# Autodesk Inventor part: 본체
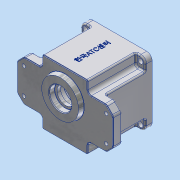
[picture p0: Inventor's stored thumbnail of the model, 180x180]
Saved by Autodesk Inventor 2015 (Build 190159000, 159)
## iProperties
Created: 2016-02
Part Number: 본체
Material: Aluminum 6061
Document SubType Name: Modeling
Designer: Administrator
Density: 2.7 g/cm^3
Appearance: Aluminum - Flat
Mass: 873.756 g
Surface Area: 761.195 cm^2
Volume: 323.613 cm^3
Author: Administrator
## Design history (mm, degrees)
sketch "Sketch1"
  geometry: L1 (70, -30)-(-70, -30); L2 (-70, -30)-(-70, 30); L3 (-70, 30)-(70, 30); L4 (70, 30)-(70, -30); L5 (70, -30)-(-70, 30); L6 (-70, -30)-(70, 30); 1 further point
  constraints: 12 end point, 2 midpoint, 2 parallel, 1 horizontal, 1 perpendicular
  dimensions: "d0" = 140 distance of L2.end L3.end; "d1" = 60 distance of L1.end L2.end
extrude "Extrusion1" new body sketch "Sketch1" distance "d2" = 13; taper "d3" = 0 deg
chamfer "Chamfer1" distance "d4" = 10; stored, may be unused: second distance "d5" = 2, angle "d6" = 45 deg
sketch "Sketch2"
  geometry: L1 (47, -47)-(-47, -47); L2 (-47, -47)-(-47, 47); L3 (-47, 47)-(47, 47); L4 (47, 47)-(47, -47); L5 (47, -47)-(-47, 47); L6 (-47, -47)-(47, 47); 1 further point
  constraints: 12 end point, 2 midpoint, 2 parallel, 1 horizontal, 1 perpendicular
  dimensions: "d7" = 94 distance of L2.end L3.end; "d8" = 94 distance of L1.end L2.end
extrude "Extrusion2" join sketch "Sketch2" distance "d9" = 80; taper "d10" = 0 deg
fillet "Fillet1" dims "d11" = 5
sketch "Sketch3"
  geometry: L1 (-47, 47)-(-47, 30) reference; L2 (-47, 30)-(-57.929, 30) reference; L3 (-57.929, -30)-(-47, -30) reference; L4 (-47, -30)-(-47, -47) reference; L5 (47, -47)-(47, -30) reference; L6 (47, -30)-(57.929, -30) reference; L7 (57.929, 30)-(47, 30) reference; L8 (47, 30)-(47, 47) reference; L9 (47, 30)-(33, 30); L10 (33, 47)-(33, 30); L11 (33, -47)-(33, -30); L12 (47, -30)-(33, -30); L13 (-33, -47)-(-33, -30); L14 (-33, 47)-(-33, 30); L15 (-47, 30)-(-33, 30); L16 (-47, -30)-(-33, -30); L17 (-47, 30)-(-47, 47); L18 (-47, 47)-(-33, 47); L19 (47, 47)-(-47, 47) reference; L20 (33, 47)-(47, 47); L21 (47, 47)-(47, 30); L22 (47, -30)-(47, -47); L23 (47, -47)-(33, -47); L24 (-47, -47)-(47, -47) reference; L25 (-33, -47)-(-47, -47); L26 (-47, -47)-(-47, -30); 1 further point
  constraints: 32 end point, 8 collinear, 4 horizontal
  dimensions: "d12" = 14 distance between parallel lines of L8 L10; "d13" = 14 distance between parallel lines of L5 L11; "d14" = 14 distance between parallel lines of L4 L13; "d15" = 14 distance between parallel lines of L1 L14
extrude "Extrusion3" cut sketch "Sketch3" distance "d16" = 70; taper "d17" = 0 deg
fillet "Fillet2" dims "d18" = 8
sketch "Sketch4"
  geometry: L1 (-60, -19)-(60, -19); L2 (60, -19)-(60, 19); L3 (60, 19)-(-60, 19); L4 (-60, 19)-(-60, -19); L5 (-60, -19)-(60, 19); L6 (60, -19)-(-60, 19); 5 further points
  constraints: 12 end point, 4 coincident, 2 midpoint, 2 parallel, 1 horizontal, 1 perpendicular
  dimensions: "d19" = 120 distance of L3.end L2.end; "d20" = 38 distance of L2.end L1.end
hole "Hole1" sketch "Sketch4" at (-60, 19), (-60, -19), (60, -19), (60, 19) diameter "d21" = 5; stored, may be unused: countersink angle "d25" = 90 deg, drill point angle "d27" = 0 deg; dims "d22" = 6, "d23" = 4, "d24" = 2, "d26" = 9
hole "Hole2" diameter "d30" = 9; stored, may be unused: countersink angle "d34" = 90 deg, drill point angle "d36" = 0 deg; dims "d28" = 10, "d29" = 10, "d31" = 6, "d32" = 4, "d33" = 2, "d35" = 4
hole "Hole3" diameter "d39" = 9; stored, may be unused: countersink angle "d43" = 90 deg, drill point angle "d45" = 0 deg; dims "d37" = 10, "d38" = 10, "d40" = 6, "d41" = 4, "d42" = 2, "d44" = 4
hole "Hole4" diameter "d48" = 9; stored, may be unused: countersink angle "d52" = 90 deg, drill point angle "d54" = 0 deg; dims "d46" = 10, "d47" = 10, "d49" = 6, "d50" = 4, "d51" = 2, "d53" = 4
hole "Hole5" diameter "d57" = 9; stored, may be unused: countersink angle "d61" = 90 deg, drill point angle "d63" = 0 deg; dims "d55" = 10, "d56" = 10, "d58" = 6, "d59" = 4, "d60" = 2, "d62" = 4
sketch "Sketch5"
  geometry: L1 (-40, -40)-(40, -40); L2 (40, -40)-(40, 40); L3 (40, 40)-(-40, 40); L4 (-40, 40)-(-40, -40); L5 (-40, -40)-(40, 40); L6 (40, -40)-(-40, 40); 5 further points
  constraints: 12 end point, 4 coincident, 2 midpoint, 2 parallel, 1 horizontal, 1 perpendicular
  dimensions: "d64" = 80 distance of L3.end L2.end; "d65" = 80 distance of L2.end L1.end
hole "Hole6" sketch "Sketch5" at (-40, 40), (-40, -40), (40, -40), (40, 40) diameter "d66" = 7; stored, may be unused: countersink angle "d70" = 90 deg, drill point angle "d72" = 0 deg; dims "d67" = 6, "d68" = 4, "d69" = 2, "d71" = 4
sketch "Sketch6"
  geometry: 2 further points
  constraints: 1 coincident
hole "Hole7" sketch "Sketch6" at (0, 0) diameter "d73" = 80; stored, may be unused: countersink angle "d77" = 90 deg, drill point angle "d79" = 0 deg; dims "d74" = 6, "d75" = 86, "d76" = 9, "d78" = 71
sketch "Sketch7"
  geometry: C1 r 28 at (0, 11); 1 further point
  constraints: 1 centre point, 1 vertical alignment
  dimensions: "d80" = 56 diameter of C1; "d81" = 11 distance of point (0, 0) C1.centre
extrude "Extrusion4" join sketch "Sketch7" distance "d82" = 7; taper "d83" = -10 deg
sketch "Sketch8"
  geometry: C1 r 21 at (0, -11); C2 r 15 at (0, 20); 1 further point
  constraints: 2 centre point, 2 vertical alignment
  dimensions: "d84" = 21 radius of C1; "d85" = 15 radius of C2; "d86" = 11 distance of point (0, 0) C1.centre; "d87" = 20 distance of C2.centre point (0, 0)
extrude "Extrusion5" join sketch "Sketch8" distance "d88" = 7; taper "d89" = 0 deg
sketch "Sketch9"
  geometry: L1 (36, 0)-(-36, 0); A1 r 36 centre (0, 0) between (-36, 0) and (36, 0); A2 r 4 centre (36, 0) between (35.852, 3.997) and (35.852, -3.997); A3 r 4 centre (-36, 0) between (-35.852, -3.997) and (-35.852, 3.997); A4 r 40 centre (0, 0) between (-39.148, 8.214) and (-39.148, -8.214) reference; A5 r 3.5 centre (-35.722, -7.495) between (-35.778, -3.995) and (-39.148, -8.214); A6 r 3.5 centre (-35.722, 7.495) between (-39.148, 8.214) and (-35.778, 3.995); A7 r 3.5 centre (35.722, -7.495) between (39.148, -8.214) and (35.778, -3.995); A8 r 3.5 centre (35.722, 7.495) between (35.778, 3.995) and (39.148, 8.214); 2 further points
  constraints: 26 point on circle, 8 tangent, 7 centre point, 4 coincident, 2 end point, 1 equal radius, 1 horizontal, 1 midpoint
  dimensions: "d90" = 36 radius of A1; "d91" = 4 radius of A2; "d92" = 4 radius of A3; "d93" = 3.5 radius of A5; "d94" = 3.5 radius of A6; "d95" = 3.5 radius of A7
extrude "Extrusion6" join sketch "Sketch9" stored distance "d96" = 7; taper "d97" = 0 deg
hole "Hole8" diameter "d100" = 25; stored, may be unused: countersink angle "d104" = 90 deg, drill point angle "d106" = 0 deg; dims "d98" = 10, "d99" = 10, "d101" = 6, "d102" = 35, "d103" = 10, "d105" = 15
hole "Hole9" diameter "d109" = 32; stored, may be unused: countersink angle "d113" = 90 deg, drill point angle "d115" = 0 deg; dims "d107" = 10, "d108" = 10, "d110" = 6, "d111" = 35, "d112" = 10, "d114" = 8
fillet "Fillet3" dims "d119" = 0.3
hole "Hole10" diameter "d122" = 19; stored, may be unused: countersink angle "d126" = 90 deg, drill point angle "d128" = 0 deg; dims "d120" = 10, "d121" = 10, "d123" = 6, "d124" = 22, "d125" = 7, "d127" = 8
fillet "Fillet4" dims "d129" = 0.3
fillet "Fillet5" dims "d130" = 2
fillet "Fillet6" dims "d131" = 5
sketch "Sketch11"
  geometry: L1 (36, 0)-(-36, 0); A1 r 36 centre (0, 0) between (36, 0) and (-36, 0); 4 further points
  constraints: 4 coincident, 2 end point, 2 point on circle, 1 centre point, 1 horizontal, 1 midpoint
  dimensions: "d132" = 36 radius of A1
hole "Hole11" sketch "Sketch11" at (36, 0), (-36, 0) diameter "d133" = 3.242; stored, may be unused: countersink angle "d137" = 90 deg, drill point angle "d139" = 118 deg; dims "d134" = 7, "d135" = 22, "d136" = 7, "d138" = 9
fillet "Fillet7" dims "d140" = 3
fillet "Fillet8" dims "d141" = 2
fillet "Fillet9" dims "d142" = 2
sketch "Sketch12"
  geometry: L1 (70, -80)-(8, -80) reference; L2 (0, 0)-(78, 0) reference; 3 further points
  constraints: 1 midpoint, 1 vertical alignment, 1 other
  dimensions: "d143" = 40 distance from line of L2 point (39, -40)
emboss "Emboss1" sketch "Sketch12" dims "d11" = 5, "d144" = 0.5, "d145" = 0
chamfer "Chamfer3" distance "d146" = 1; stored, may be unused: second distance "d147" = 2, angle "d148" = 45 deg
sketch "Sketch14"
  geometry: L1 (31, 47)-(-31, 47) reference; L2 (-33, 45)-(-33, 35) reference; L3 (-38, 30)-(-57.929, 30) reference; L4 (-68.536, 21.464)-(-61.464, 28.536) reference; L5 (-70, 17.929)-(-70, -17.929) reference; L6 (-61.464, -28.536)-(-68.536, -21.464) reference; L7 (-57.929, -30)-(-38, -30) reference; L8 (-33, -35)-(-33, -45) reference; L9 (-31, -47)-(31, -47) reference; L10 (33, -45)-(33, -35) reference; L11 (38, -30)-(57.929, -30) reference; L12 (68.536, -21.464)-(61.464, -28.536) reference; L13 (70, -17.929)-(70, 17.929) reference; L14 (61.464, 28.536)-(68.536, 21.464) reference; L15 (57.929, 30)-(38, 30) reference; L16 (33, 35)-(33, 45) reference; L17 (-31, 46)-(31, 46); L18 (32, 45)-(32, 35); L19 (38, 29)-(57.929, 29); L20 (60.757, 27.828)-(67.828, 20.757); L21 (69, 17.929)-(69, -17.929); L22 (67.828, -20.757)-(60.757, -27.828); L23 (57.929, -29)-(38, -29); L24 (32, -35)-(32, -45); L25 (31, -46)-(-31, -46); L26 (-32, -45)-(-32, -35); L27 (-38, -29)-(-57.929, -29); L28 (-60.757, -27.828)-(-67.828, -20.757); L29 (-69, -17.929)-(-69, 17.929); L30 (-67.828, 20.757)-(-60.757, 27.828); L31 (-57.929, 29)-(-38, 29); L32 (-32, 35)-(-32, 45); C1 r 2.5 at (60, 19) reference; C2 r 2.5 at (-60, -19) reference; C3 r 2.5 at (-60, 19) reference; C4 r 2.5 at (60, -19) reference; C5 r 28.252 at (0, 11) reference; A1 r 2 centre (31, 45) between (33, 45) and (31, 47) reference; A2 r 2 centre (-31, 45) between (-31, 47) and (-33, 45) reference; A3 r 5 centre (-38, 35) between (-38, 30) and (-33, 35) reference; A4 r 5 centre (-57.929, 25) between (-57.929, 30) and (-61.464, 28.536) reference; A5 r 5 centre (-65, 17.929) between (-68.536, 21.464) and (-70, 17.929) reference; A6 r 5 centre (-65, -17.929) between (-70, -17.929) and (-68.536, -21.464) reference; A7 r 5 centre (-57.929, -25) between (-61.464, -28.536) and (-57.929, -30) reference; A8 r 5 centre (-38, -35) between (-33, -35) and (-38, -30) reference; A9 r 2 centre (-31, -45) between (-33, -45) and (-31, -47) reference; A10 r 2 centre (31, -45) between (31, -47) and (33, -45) reference; A11 r 5 centre (38, -35) between (38, -30) and (33, -35) reference; A12 r 5 centre (57.929, -25) between (57.929, -30) and (61.464, -28.536) reference; A13 r 5 centre (65, -17.929) between (68.536, -21.464) and (70, -17.929) reference; A14 r 5 centre (65, 17.929) between (70, 17.929) and (68.536, 21.464) reference; A15 r 5 centre (57.929, 25) between (61.464, 28.536) and (57.929, 30) reference; A16 r 5 centre (38, 35) between (33, 35) and (38, 30) reference; A17 r 1 centre (31, 45) between (32, 45) and (31, 46); A18 r 6 centre (38, 35) between (32, 35) and (38, 29); A19 r 4 centre (57.929, 25) between (60.757, 27.828) and (57.929, 29); A20 r 4 centre (65, 17.929) between (69, 17.929) and (67.828, 20.757); A21 r 4 centre (65, -17.929) between (67.828, -20.757) and (69, -17.929); A22 r 4 centre (57.929, -25) between (57.929, -29) and (60.757, -27.828); A23 r 6 centre (38, -35) between (38, -29) and (32, -35); A24 r 1 centre (31, -45) between (31, -46) and (32, -45); A25 r 1 centre (-31, -45) between (-32, -45) and (-31, -46); A26 r 6 centre (-38, -35) between (-32, -35) and (-38, -29); A27 r 4 centre (-57.929, -25) between (-60.757, -27.828) and (-57.929, -29); A28 r 4 centre (-65, -17.929) between (-69, -17.929) and (-67.828, -20.757); A29 r 4 centre (-65, 17.929) between (-67.828, 20.757) and (-69, 17.929); A30 r 4 centre (-57.929, 25) between (-57.929, 29) and (-60.757, 27.828); A31 r 6 centre (-38, 35) between (-38, 29) and (-32, 35); A32 r 1 centre (-31, 45) between (-31, 46) and (-32, 45); 1 further point
  constraints: 32 end point, 32 point on circle, 16 centre point, 31 other
  dimensions: "d152" = 1 distance between parallel lines of L1 L17
extrude "Extrusion7" cut sketch "Sketch14" distance "d153" = 1; taper "d154" = 0 deg
body "Solid1"
node "Projected Loop1"
